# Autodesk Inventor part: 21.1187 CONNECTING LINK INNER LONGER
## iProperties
Created: 2007-08
Part Number: 21.1187 CONNECTING LINK INNER LONGER
Document SubType Name: Modeling
Designer: Andy Moles
Density: 1 g/cm^3
Author: Andy Moles
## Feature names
1. Extrusion1
2. Extrusion2
3. Extrusion3
